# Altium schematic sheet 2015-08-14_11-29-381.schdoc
size 539 x 193 mm; SheetNumber: 1; SheetTotal: 1
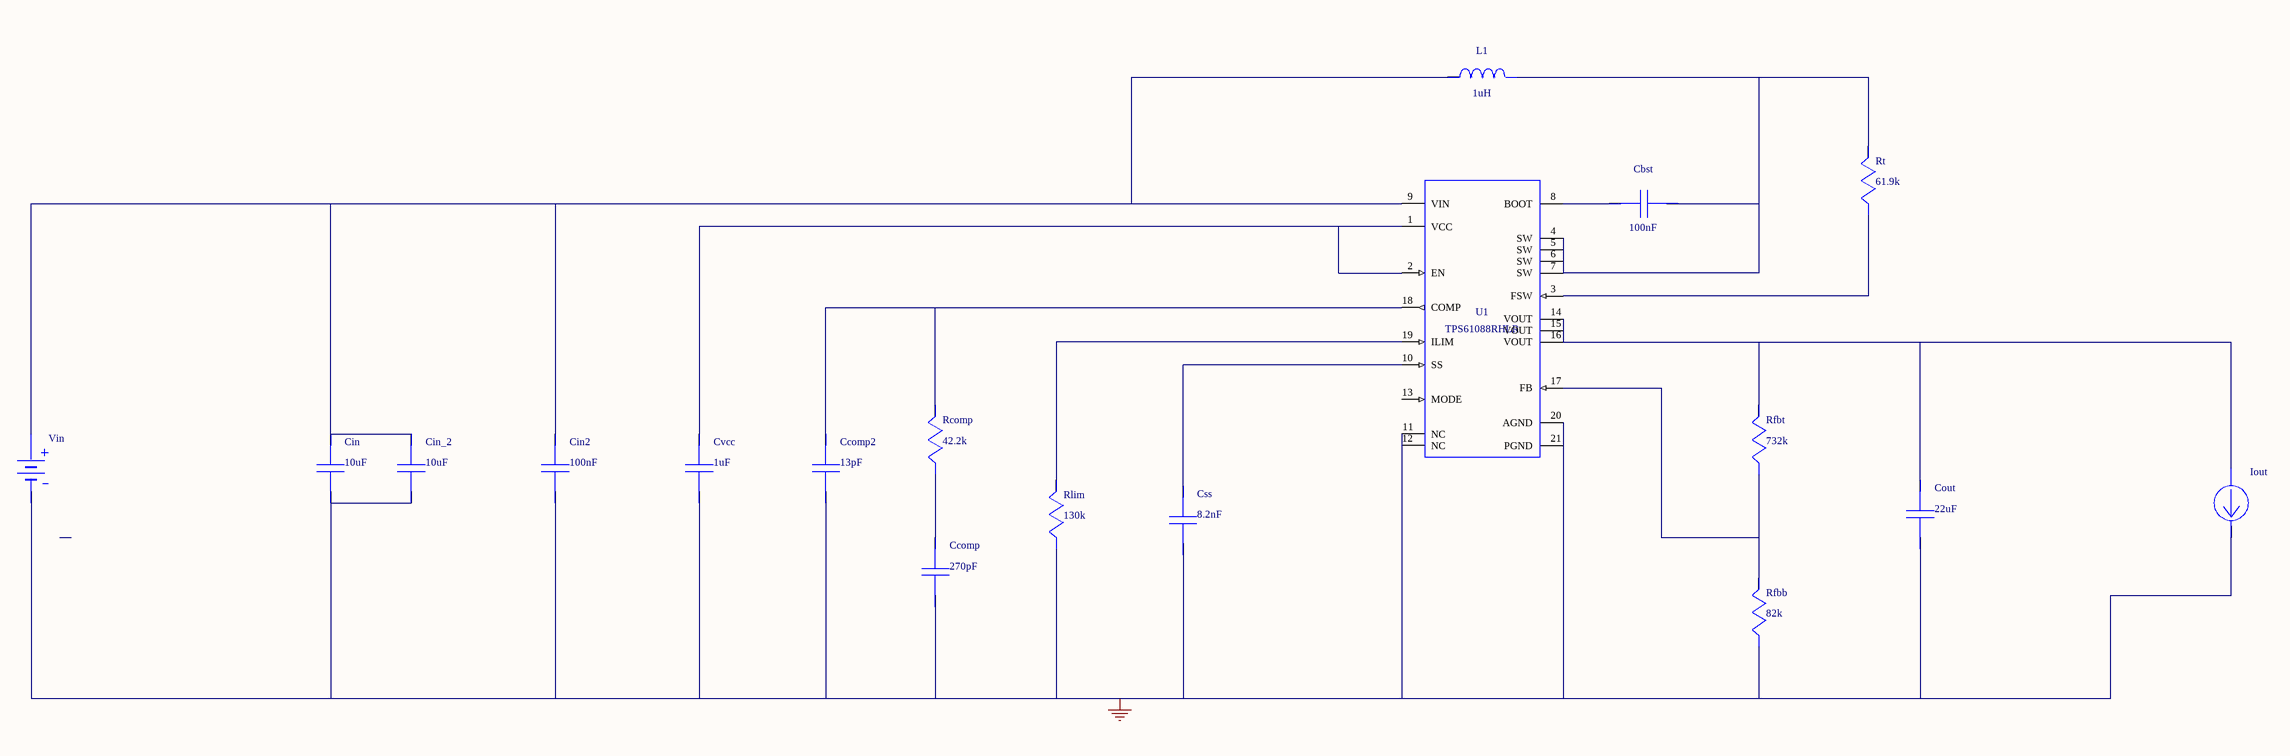
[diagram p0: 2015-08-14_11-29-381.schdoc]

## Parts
Cbst  value 100nF  (hidden comment: C1005X5R1A104K)
Ccomp  value 270pF  (hidden comment: GRM033R71E271KA01D)
Ccomp2  value 13pF  (hidden comment: C0402C0G1C130G)
Cin  value 10uF  (hidden comment: GRM188R61C106MA73D)
Cin2  value 100nF  (hidden comment: GRM155R61C104KA88D)
Cin_2  value 10uF  (hidden comment: GRM188R61C106MA73D)
Cout  value 22uF  (hidden comment: C3216X5R1E226M)
Css  value 8.2nF  (hidden comment: GRM155R71C822KA01D)
Cvcc  value 1uF  (hidden comment: C1608X5R1A105K)
Iout  WB_CURRENT_LOAD  (value not drawn)
L1  value 1uH  (hidden comment: XAL4020-102MEB)
Rcomp  value 42.2k  (hidden comment: CRCW040242K2FKED)
Rfbb  value 82k  (hidden comment: RR1220P-823-D)
Rfbt  value 732k  (hidden comment: CRCW0402732KFKED)
Rlim  value 130k  (hidden comment: ERJ-8ENF1303V)
Rt  value 61.9k  (hidden comment: ERJ-8ENF6192V)
U1  TPS61088RHLR
Vin  WB_BATTERY  (value not drawn)

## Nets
0: Ccomp.2 Ccomp2.2 Cin.2 Cin2.2 Cin_2.2 Cout.2 Css.2 Cvcc.2 Iout.2(-) Rfbb.2 Rlim.2 U1.11(NC) U1.12(NC) U1.20(AGND) U1.21(PGND) Vin.2(-)
NetCbst_1: Cbst.1 U1.8(BOOT)
NetCbst_2: Cbst.2 L1.2 Rt.1 U1.4(SW) U1.5(SW) U1.6(SW) U1.7(SW)
NetCcomp2_1: Ccomp2.1 Rcomp.1 U1.18(COMP)
NetCcomp_1: Ccomp.1 Rcomp.2
NetCin_1: Cin.1 Cin2.1 Cin_2.1 L1.1 U1.9(VIN) Vin.1(+)
NetCout_1: Cout.1 Iout.1(+) Rfbt.1 U1.14(VOUT) U1.15(VOUT) U1.16(VOUT)
NetCss_1: Css.1 U1.10(SS)
NetCvcc_1: Cvcc.1 U1.1(VCC) U1.2(EN)
NetRfbb_1: Rfbb.1 Rfbt.2 U1.17(FB)
NetRlim_1: Rlim.1 U1.19(ILIM)
NetRt_2: Rt.2 U1.3(FSW)

Not connected (* = marked no-connect by the designer): U1 13(MODE)

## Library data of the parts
Cbst = C1005X5R1A104K: Manufacturer Name: TDK
Ccomp = GRM033R71E271KA01D: GRM033R71E271KA0; Manufacturer Name: MuRata
Ccomp2 = C0402C0G1C130G: Manufacturer Name: TDK
Cin Cin_2 = GRM188R61C106MA73D: GRM188R61C106MA7; Manufacturer Name: MuRata
Cin2 = GRM155R61C104KA88D: GRM155R61C104KA8; Manufacturer Name: MuRata
Cout = C3216X5R1E226M: Manufacturer Name: TDK
Css = GRM155R71C822KA01D: GRM155R71C822KA0; Manufacturer Name: MuRata
Cvcc = C1608X5R1A105K: Manufacturer Name: TDK
Iout = WB_CURRENT_LOAD: Value: UNLISTED
L1 = XAL4020-102MEB: Manufacturer Name: Coilcraft
Rcomp = CRCW040242K2FKED: Manufacturer Name: Vishay-Dale
Rfbb = RR1220P-823-D: Manufacturer Name: Susumu Co Ltd
Rfbt = CRCW0402732KFKED: Manufacturer Name: Vishay-Dale
Rlim = ERJ-8ENF1303V: Manufacturer Name: Panasonic
Rt = ERJ-8ENF6192V: Manufacturer Name: Panasonic
U1 = TPS61088RHLR: Manufacturer Name: Texas Instruments; Value: UNLISTED
Vin = WB_BATTERY: Value: UNLISTED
